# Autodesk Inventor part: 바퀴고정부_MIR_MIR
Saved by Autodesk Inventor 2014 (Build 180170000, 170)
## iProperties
Created: 2015-05
Part Number: 바퀴고정부_MIR_MIR
Material: 일반
Vendor: CBT Solutions
Document SubType Name: 모델링
Designer: Administrator
Appearance: 기본값
Company: 한국ATC센터
Author: KYOUNG IL JANG
Comments: 파생
d0: 1.000 ul
d0_1: 1.000 ul
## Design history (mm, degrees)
derived "바퀴고정부_MIR.ipt"
feature "솔리드1::바퀴고정부_MIR.ipt"
tag "피쳐 태그1"
node "솔리드1"
other parameters: "d0" = 1, "d0_1" = 1
